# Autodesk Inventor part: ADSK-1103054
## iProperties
Shininess: 41.0
Length Units: 11272
Angle Units: 11279
Time Units: 11290
Mass Units: 11286
Length Display Precision: 4
Angle Display Precision: 2
Compacted: True
Created: 2000-08
Part Number: ADSK-1103054
Document SubType Name: Modeling
Description: THRUST WASHER
Mass: 0.825593 g
Surface Area: 2.67042 cm^2
Volume: 0.102177 cm^3
Density: 8.08 g/cm^3
Material: Stainless Steel
Density: 0.0
Volumn: 0.0
Area: 0.0
PropertySet Name: Model Information
Control State: 0
Master: False
Checked Out: False
Author: Autodesk, Inc.
